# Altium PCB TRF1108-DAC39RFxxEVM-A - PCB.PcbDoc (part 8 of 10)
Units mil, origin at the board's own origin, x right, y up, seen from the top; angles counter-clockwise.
Board outline 4951.22 x 2726.56 mil, 16 copper layers (Top Layer, L2 GND1, L3 PWR1, L4 GND2, L5 PWR2, L6 GND3, L7 Ctrl Signal 1, L8 GND4, L9 GND5, L10 Ctrl Signal 2, L11 GND6, L12 PWR3, L13 GND7, L14 PWR4, L15 GND8, Bottom Layer), stack 80.2 mil thick; 705 components, 433 nets, 3633 pads, 1678 vias.
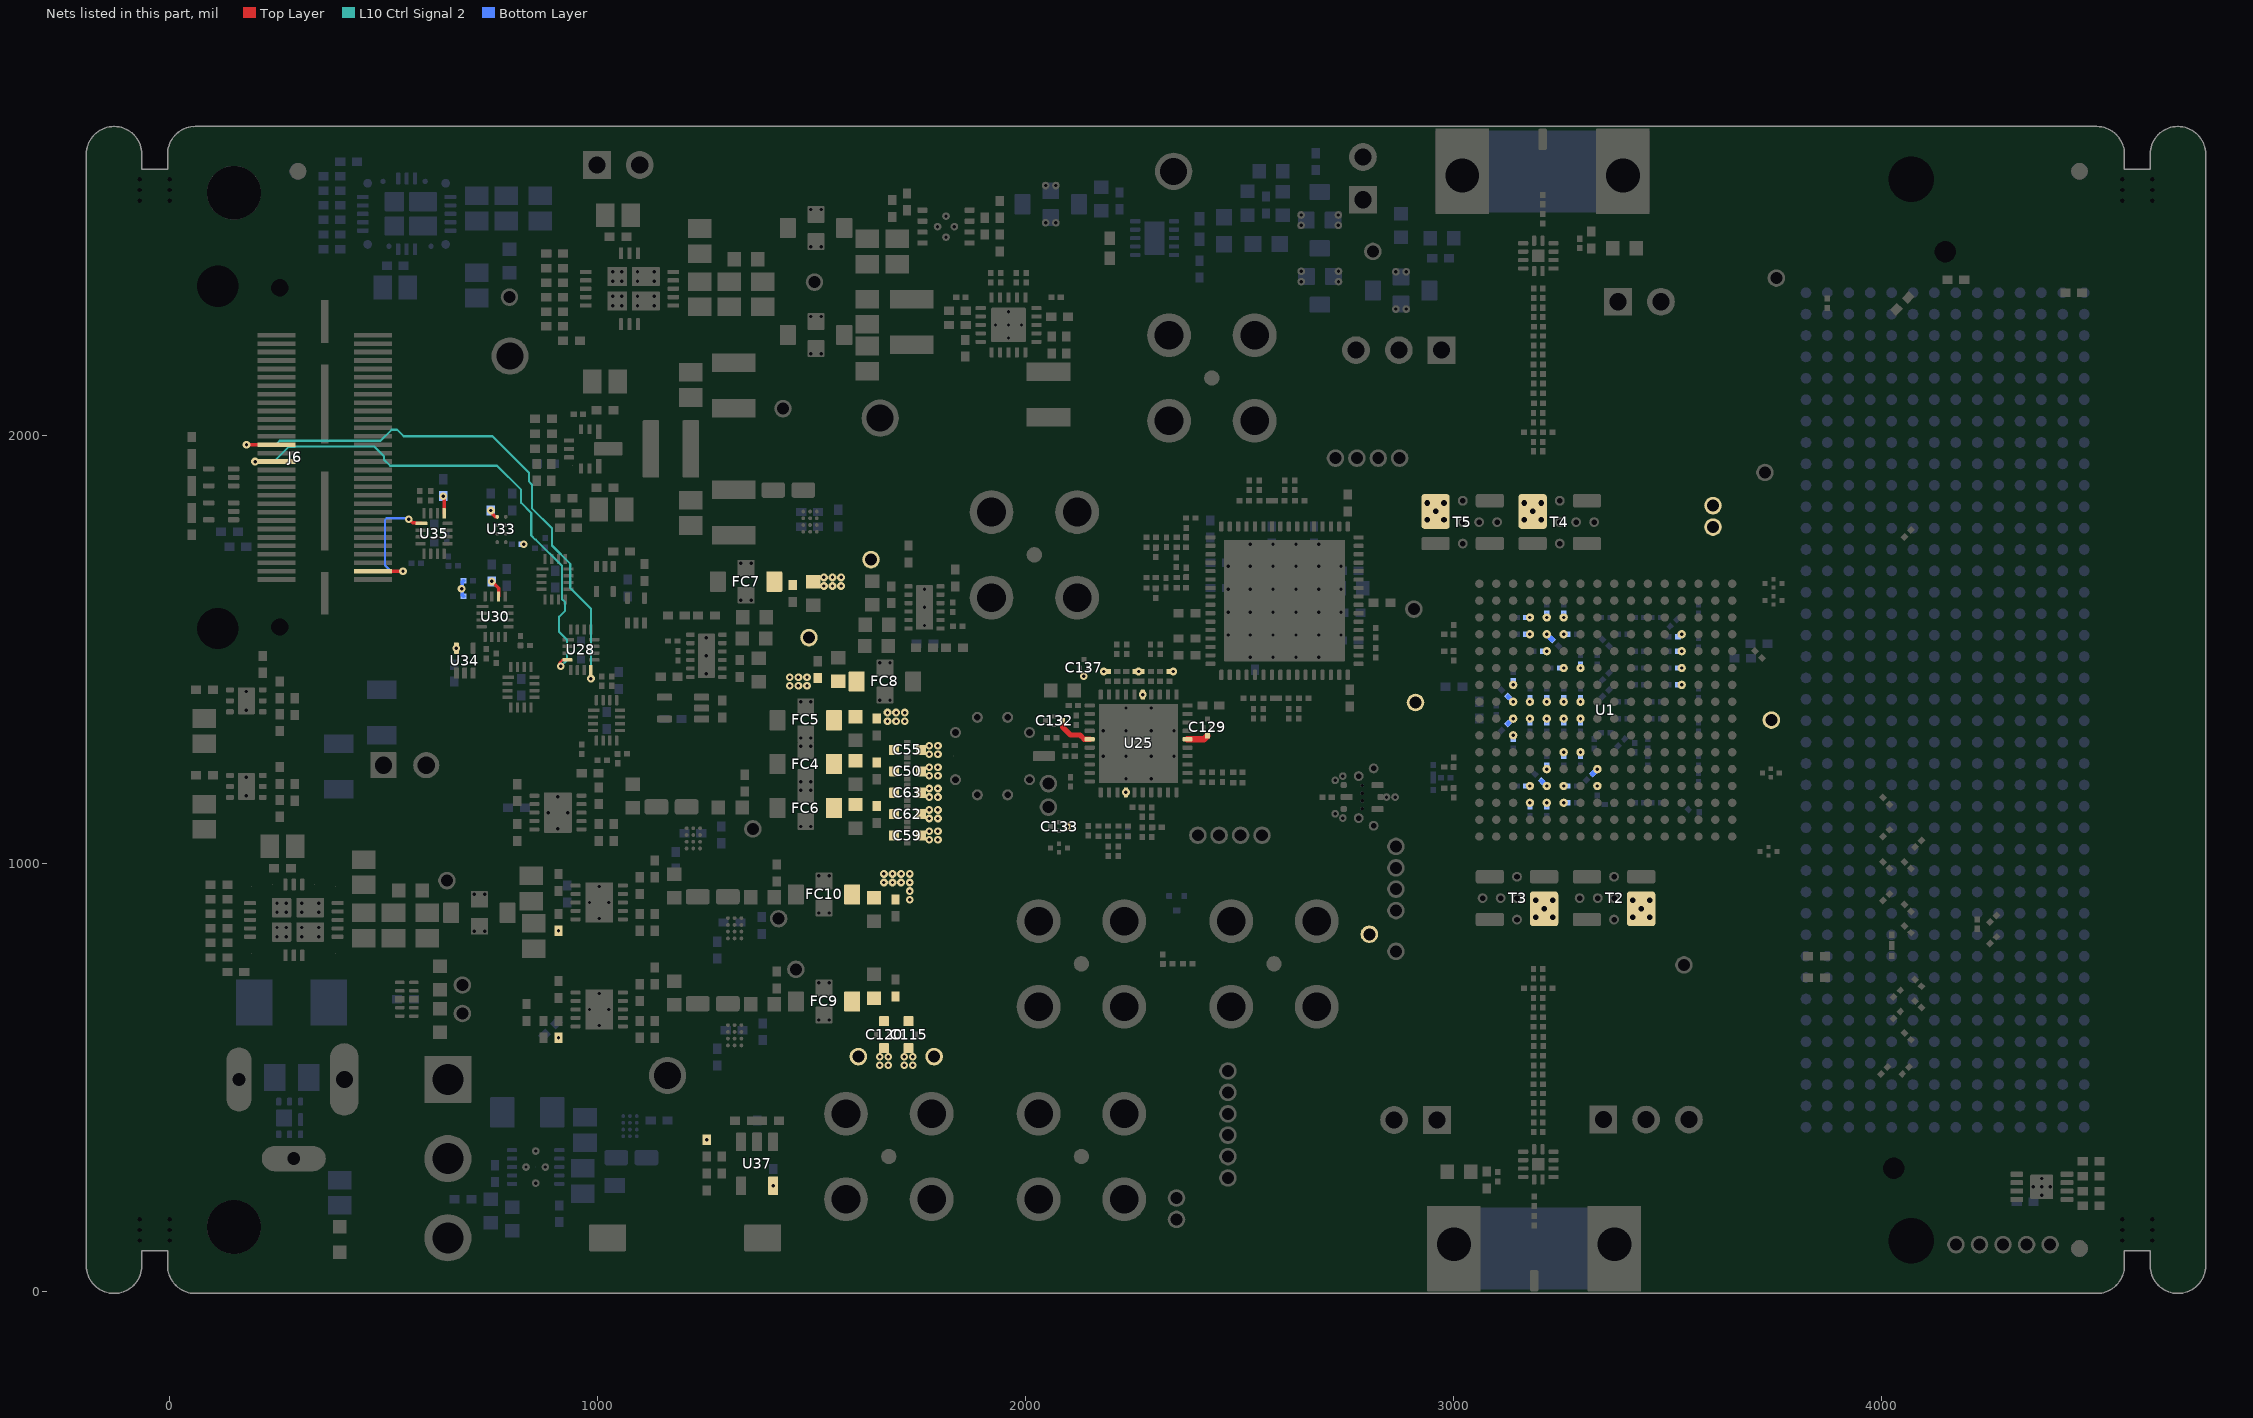
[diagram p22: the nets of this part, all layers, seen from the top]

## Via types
v1: diameter 18, hole 8, Top Layer to Bottom Layer, tented both sides, 1468 vias
v2: diameter 20, hole 10.01, Top Layer to Bottom Layer, 187 vias
v3: diameter 19.68, hole 7.87, Top Layer to Bottom Layer, tented both sides, 16 vias
v4: diameter 19.68, hole 7.87, Top Layer to Bottom Layer, 6 vias
v5: diameter 18/18/18/18/18/18/18/18/18/18/18/18/18/18/18/18 (per signal layer), hole 8, Top Layer to Bottom Layer, tented both sides, 1 vias

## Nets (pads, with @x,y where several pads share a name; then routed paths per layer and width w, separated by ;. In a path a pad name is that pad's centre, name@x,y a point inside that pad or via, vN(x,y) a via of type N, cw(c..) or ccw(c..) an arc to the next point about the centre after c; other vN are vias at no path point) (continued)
USB_LMX_SDI: J6.30 U28.4 | length 1237.6
  Top Layer w5: v1@908.95,1460.17 911.44,1462.66 911.44,1469.01 917.14,1474.72 928.49,1474.72 U28.4@928.95,1475.17
  Top Layer w8: v1(199.41,1938.46) J6.30@249.41,1938.46
  L10 Ctrl Signal 2 w5: v1(199.41,1938.46) 242.95,1938.46 276.83,1972.34 291.68,1972.34 292.99,1973.65 478.02,1973.65 500.29,1951.38 500.29,1943.48 514.96,1928.82 764.61,1928.82 821,1872.43 821,1841.97 844.64,1818.33 844.64,1765.74 854.14,1756.24 855.36,1756.24 916.5,1695.1 916.5,1617.2 923.82,1609.88 923.82,1590.13 909.92,1576.23 909.92,1540.33 928.37,1521.88 928.37,1474.59 v1(913.95,1460.17)
USB_LMX_SDO: J6.34 U28.8 | length 1347
  Top Layer w5: v1(984.07,1431.55) U28.8@984.07,1451.55
  Top Layer w8: v1(179.41,1977.83) J6.34@249.41,1977.83
  L10 Ctrl Signal 2 w5: v1(179.41,1977.83) 247.9,1977.83 257.09,1987.02 492.58,1987.02 518.58,2013.02 531.42,2013.02 546.92,1997.52 754.32,1997.52 839.04,1912.81 839.04,1892.18 846.09,1885.13 846.09,1829.61 893.07,1782.63 893.07,1742.32 935.95,1699.45 935.95,1643.29 984.07,1595.17 v1(984.07,1431.55)
USB_SCLK_DAC: J6.3 U35.1 | length 315.4
  Top Layer w8: J6.3@475,1682.56 v1(545,1682.56) ; v1(558.17,1804.05) 559.11,1804.05 567.86,1795.3 573.24,1795.3 574.5,1794.05 U35.1@588.17,1794.05
  Bottom Layer w5: v1(545,1682.56) 516.91,1682.56 502.72,1696.75 502.72,1801.7 507.18,1806.16 556.06,1806.16 v1(558.17,1804.05)
VCC01: C129.3 U25.16 | length 50.2
  Top Layer w15: U25.16@2377.76,1289.83 2416.39,1289.83 C129.3@2424.57,1298.02
VCC23: C132.3 U25.35 | length 90.3
  Top Layer w12: C132.3@2085.88,1333.18 2085.88,1318.12 2104.25,1299.75 2126.63,1299.75 2136.55,1289.83 U25.35@2149.41,1289.83
VCCCLKIN: C133.3 U25.4
  other v1: 2097.41,1085.82 2234.06,1165.82
VCCLOGIC: C137.3 R129.1 R130.1 R131.1 R132.1 U25.25 | length 35
  Top Layer w6: R130.1@2256.11,1448.17 v1(2263.59,1448.17) R131.1@2271.07,1448.17
  Top Layer w10: v1(2182.33,1448.17) R129.1@2192.33,1448.17 ; R132.1@2334.85,1448.17 v1(2344.85,1448.17)
  other v1: 2273.43,1394.17 2135.79,1437.02
VDDA: C50.1 C53.2 C54.2 C55.1 FC4.3
VDDA18A: C50.3 C248.2 C249.2 PP5.1 T2.3 T3.3 U1.G14 U1.H14 | length 25.5
  Bottom Layer w5: C248.2@3138.55,1290.07 v1(3138.55,1298.73)
  Bottom Layer w10: C249.2@3126.66,1326.21 v1(3138.55,1338.1)
  other v1: 1774.86,1204.73 1794.86,1204.73 1774.86,1224.73 1794.86,1224.73
VDDA18B: C55.3 C250.2 C251.2 PP6.1 T4.3 T5.3 U1.J14 U1.K14 | length 25.5
  Bottom Layer w5: v1(3138.55,1416.84) C251.2@3138.55,1425.5
  Bottom Layer w10: C250.2@3126.66,1389.36 v1(3138.55,1377.47)
  other v1: 1774.86,1254.73 1794.86,1254.73 1774.86,1274.73 1794.86,1274.73
VDDCLK10: C126.2 C127.2 C219.2 C220.2 C221.2 C222.2 C223.2 C224.2 FC10.3 U1.E12 U1.F11 U1.H11 U1.J11 U1.L11 U1.M12 | length 52
  Bottom Layer w5: C224.2@3208.62,1495.58 v1(3217.29,1495.58) ; v1(3217.29,1219.99) C219.2@3217.29,1228.65 ; C223.2@3248,1456.21 v1(3256.66,1456.21) ; C220.2@3256.66,1250.7 v1(3256.66,1259.36) ; C221.2@3256.66,1329.44 v1(3256.66,1338.1) ; v1(3256.66,1377.47) C222.2@3256.66,1386.13
  other v1: 1728.69,915.14 1728.69,935.14 1668.69,955.14 1688.69,955.14 1708.69,955.14 1728.69,955.14 1668.69,975.14 1688.69,975.14 1708.69,975.14 1728.69,975.14
VDDCLK18: C59.3 C225.2 C226.2 PP7.1 U1.H12 U1.H13 | length 17.3
  Bottom Layer w5: C226.2@3177.92,1329.44 v1(3177.92,1338.1) ; C225.2@3217.29,1329.44 v1(3217.29,1338.1)
  other v1: 1774.86,1054.73 1794.86,1054.73 1774.86,1074.73 1794.86,1074.73
VDDCSR: C59.1 C60.2 C61.2 C62.1 C63.1 FC6.3
VDDIO: C57.2 C58.2 C163.1 C166.1 C170.2 C172.2 C256.2 C257.2 FC5.3 R95.2 R104.2 R152.1 R153.1 R160.2 R170.2 U1.D9 U1.E9 U30.14 U33.A1 U34.5 U35.13 U37.5 | length 164.3
  Top Layer w8: v1(639.08,1857.84) 639.08,1855.13 641.32,1852.88 U35.13@641.32,1817.67 ; v1(750.54,1824.21) 750.54,1821.5 755,1817.05 755,1814.97 760.55,1809.41 U33.A1@765.34,1809.41 U33.A1@765.54,1809.21 ; v1(752.57,1658.54) 768.32,1642.79 U30.14@768.32,1623.54
  Bottom Layer w8: R153.1@686.9,1624.17 686.11,1624.17 683.81,1626.47 683.81,1636.9 681.9,1638.81 v1(681.9,1641.52) 681.9,1644.22 683.81,1646.14 683.81,1657.62 686.11,1659.91 R152.1@686.9,1659.91
  Bottom Layer w10: C257.2@3323.51,1208.1 v1(3335.4,1219.99)
  other v1: 1409.63,246.59 1254.63,354.1 908.37,592.32 908.37,842.32 3335.4,1180.62 1677.02,1332.09 1697.02,1332.09 1717.02,1332.09 1677.02,1352.09 1697.02,1352.09 1717.02,1352.09 669.58,1502.67 827.07,1745.36
VDDL: C115.1 C118.2 C119.2 C120.1 FC9.3
VDDLA: C115.3 C242.2 C243.2 PP14.1 U1.F10 U1.H10 | length 17.3
  Bottom Layer w5: C242.2@3296.03,1250.7 v1(3296.03,1259.36) ; C243.2@3296.03,1329.44 v1(3296.03,1338.1)
  other v1: 1716.05,528.18 1736.05,528.18 1716.05,548.18 1736.05,548.18
VDDLB: C120.3 C244.2 C245.2 PP15.1 U1.J10 U1.L10 | length 17.3
  Bottom Layer w5: v1(3296.03,1377.47) C244.2@3296.03,1386.13 ; v1(3296.03,1456.21) C245.2@3296.03,1464.87
  other v1: 1658.86,528.18 1678.86,528.18 1658.86,548.18 1678.86,548.18
VDDR: C63.3 C258.2 C259.2 C260.2 C261.2 PP9.1 U1.K4 U1.L4 U1.M4 U1.N4 | length 34.6
  Bottom Layer w5: C259.2@3523.59,1416.84 v1(3532.25,1416.84) ; C260.2@3523.59,1456.21 v1(3532.25,1456.21) ; C258.2@3523.59,1495.58 v1(3532.25,1495.58) ; C261.2@3523.59,1534.95 v1(3532.25,1534.95)
  other v1: 1774.86,1154.73 1794.86,1154.73 1774.86,1174.73 1794.86,1174.73
VDDSYS18: C62.3 C246.2 C247.2 PP8.1 U1.J12 U1.J13 | length 17.3
  Bottom Layer w5: v1(3177.92,1377.47) C247.2@3177.92,1386.13 ; v1(3217.29,1377.47) C246.2@3217.29,1386.13
  other v1: 1774.86,1104.73 1794.86,1104.73 1774.86,1124.73 1794.86,1124.73
VEExA: C101.2 C102.2 C236.1 C237.1 C238.1 C239.1 C240.1 C241.1 FC7.3 PP11.1 U1.C11 U1.C12 U1.C13 U1.D11 U1.D12 U1.D13 | length 60.1
  Bottom Layer w5: C238.1@3169.26,1180.62 v1(3177.92,1180.62) ; C236.1@3177.92,1132.59 v1(3177.92,1141.25) ; C239.1@3217.29,1132.59 v1(3217.29,1141.25) ; v1(3256.66,1141.25) C240.1@3265.32,1141.25 ; v1(3256.66,1180.62) C241.1@3265.32,1180.62
  Bottom Layer w10: C237.1@3205.4,1192.51 v1(3217.29,1180.62)
  other v1: 1528.48,1647.88 1548.48,1647.88 1568.48,1647.88 1528.48,1667.88 1548.48,1667.88 1568.48,1667.88
VEExB: C109.2 C110.2 C213.1 C214.1 C215.1 C216.1 C217.1 C218.1 FC8.3 PP12.1 U1.N11 U1.N12 U1.N13 U1.P11 U1.P12 U1.P13 | length 60.1
  Bottom Layer w5: C214.1@3169.26,1534.95 v1(3177.92,1534.95) ; C213.1@3169.26,1574.32 v1(3177.92,1574.32) ; v1(3217.29,1574.32) C218.1@3217.29,1582.98 ; v1(3256.66,1534.95) C216.1@3265.32,1534.95 ; v1(3256.66,1574.32) C217.1@3256.66,1582.98
  Bottom Layer w12: v1(3217.29,1534.95) C215.1@3229.18,1523.06
  other v1: 1448.87,1414.74 1468.87,1414.74 1488.87,1414.74 1448.87,1434.74 1468.87,1434.74 1488.87,1434.74
pads on no net: FID1.1 FID2.1 FID3.1 fid4.1 fid5.1 fid6.1 H3. H4. J1. J1.A2 J1.A3 J1.A6 J1.A7 J1.A10 J1.A11 J1.A14 J1.A15 J1.A18 J1.A19 J1.B1 J1.B4 J1.B5 J1.B8 J1.B9 J1.B12 J1.B13 J1.B16 J1.B17 J1.B40 J1.C6 J1.C7 J1.C10 J1.C11 J1.C14 J1.C15 J1.C16 J1.C18 J1.C19 J1.C22 J1.C23 J1.C39 J1.D8 J1.D9 J1.D11 J1.D12 J1.D14 J1.D15 J1.D16 J1.D17 J1.D18 J1.D20 J1.D21 J1.D23 J1.D24 J1.D29 J1.D33 J1.D34 J1.D36 J1.D38 J1.D40 J1.E2 J1.E3 J1.E6 J1.E7 J1.E9 J1.E10 J1.E12 J1.E13 J1.E15 J1.E16 J1.E17 J1.E18 J1.E19 J1.E21 J1.E22 J1.E24 J1.E25 J1.E27 J1.E28 J1.E30 J1.E31 J1.E33 J1.E34 J1.E36 J1.E37 J1.E39 J1.F4 J1.F5 J1.F7 J1.F8 J1.F10 J1.F11 J1.F13 J1.F14 J1.F15 J1.F16 J1.F17 J1.F18 J1.F19 J1.F20 J1.F22 J1.F23 J1.F25 J1.F26 J1.F28 J1.F29 J1.F31 J1.F32 J1.F34 J1.F35 J1.F37 J1.F38 J1.F40 J1.G2 J1.G3 J1.G15 J1.G16 J1.G17 J1.G18 J1.G19 J1.G21 J1.G22 J1.G24 J1.G25 J1.G39 J1.H1 J1.H4 J1.H5 J1.H7 J1.H8 J1.H10 J1.H11 J1.H13 J1.H14 J1.H15 J1.H16 J1.H17 J1.H19 J1.H20 J1.H22 J1.H23 J1.H40 J1.J2 J1.J3 J1.J4 J1.J5 J1.J6 J1.J7 J1.J9 J1.J10 J1.J12 J1.J13 J1.J15 J1.J16 J1.J17 J1.J18 J1.J19 J1.J21 J1.J22 J1.J24 J1.J25 J1.J27 J1.J28 J1.J30 J1.J31 J1.J33 J1.J34 J1.J36 J1.J37 J1.J39 J1.K1 J1.K2 J1.K3 J1.K4 J1.K5 J1.K7 J1.K8 J1.K10 J1.K11 J1.K12 J1.K13 J1.K14 J1.K15 J1.K16 J1.K17 J1.K19 J1.K20 J1.K22 J1.K23 J1.K25 J1.K26 J1.K28 J1.K29 J1.K31 J1.K32 J1.K34 J1.K35 J1.K37 J1.K38 J1.K40 J1.L3 J1.L4 J1.L5 J1.L7 J1.L8 J1.L9 J1.L10 J1.L12 J1.L13 J1.L15 J1.L16 J1.L17 J1.L19 J1.L20 J1.L21 J1.L24 J1.L25 J1.L28 J1.L29 J1.M2 J1.M3 J1.M4 J1.M5 J1.M6 J1.M7 J1.M10 J1.M11 J1.M12 J1.M14 J1.M15 J1.M17 J1.M18 J1.M19 J1.M20 J1.M22 J1.M23 J1.M26 J1.M27 J1.M30 J1.M31 J1.M34 J1.M35 J1.M38 J1.M39 J1.Y2 J1.Y3 J1.Y10 J1.Y11 J1.Y14 J1.Y15 J1.Y18 J1.Y19 J1.Y22 J1.Y23 J1.Y34 J1.Y35 J1.Y38 J1.Y39 J1.Z4 J1.Z5 J1.Z12 J1.Z13 J1.Z16 J1.Z17 J1.Z20 J1.Z21 J1.Z32 J1.Z33 J1.Z36 J1.Z37 J1.Z40 J2.3 J6.4@112.2,1548.31 J6.4@112.2,2348.31 J6.12 J6.15 J6.16 J6.17 J6.18 J6.21 J6.22 J6.23 J6.24 J6.39 J6.40 J6.41 J6.42 J6.45 J6.46 J6.47 J6.48 J6.51 J6.52 J6.53 J6.54 J6.55 J6.56 J6.57 J6.58 J6.59 J6.60 J6.MH1 J6.MH2 LBL1.0 Q1.0 SH-J13.0 SH-J14.0 SH-J17.0 SH-J18.0 T2.4 T3.4 T4.4 T5.4 U2.9 U3.A3 U3.B2 U3.C2 U4.7@179.22,1361.89 U4.7@179.22,1397.32 U5.3 U5.7@179.22,1161.89 U5.7@179.22,1197.32 U7.4 U10.A3 U10.B2 U10.C2 U11.4 U12.A3 U12.B2 U12.C2 U14.1 U14.2 U14.7 U14.8 U14.9 U14.13 U14.14 U14.15 U14.16 U14.22 U14.23 U14.29 U14.30 U14.31 U14.32 U14.40 U14.41 U14.43 U14.44 U14.46 U14.48 U14.49 U14.50 U14.51 U14.52 U14.59 U14.60 U14.61 U14.62 U14.63 U15.2 U15.11 U16.1 U17.2 U17.11 U18.A3 U18.B2 U18.C2 U20.A3 U20.B2 U20.C2 U25.18 U25.19 U25.21 U25.22 U25.29 U25.30 U27.3@537.69,682.32 U27.8@570.56,682.32 U30.4 U39.4 U40.11@2301.04,2439.12 U40.11@2301.04,2482.03

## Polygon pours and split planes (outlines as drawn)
VDDLB on L5 PWR2 "L5 PWR2-VDDLB" (solid, pour order 79): 467.47,0 4561.81,0 4561.81,2327.76 3284.03,2327.76 3284.03,1360 3845.9,1360 3845.9,415 1705.65,415 1705.65,577.74 467.47,577.74
GND on L5 PWR2 "L5_PWR2_GND_P111" (solid, remove dead copper, pour order 111): 3033.42,2342.8 3033.42,2132.24 3269.02,2132.24 3269.02,2342.8 4561.81,2342.8 4561.81,2716.54 0,2716.54 0,0 446,0 446,2342.8
5p5V_TRF_DCDC on L5 PWR2 "L5_PWR2_5P5V_TRF_DCDC_P110" (solid, remove dead copper, pour order 110): 3018.12,2631.37 3018.12,2132.24 309.41,2132.24 309.41,2631.37
VDDCLK10 on L5 PWR2 "L5 PWR2-VDDCLK10" (solid, pour order 44): 473.65,896.46 3268.98,896.46 3268.98,1232.32 3268.98,1484.8 3268.98,2105.59 473.65,2105.59
VDDLA on L5 PWR2 "L5_PWR2_VDDLA_P075" (solid, pour order 75): 1705.65,577.74 1705.65,415 3829.92,415 3829.92,1349.14 3284.03,1349.14 3284.03,879.93 467.47,879.93 467.47,577.74
5V_TRF on Bottom Layer "BOTTOM_LAYER_5V_TRF_P109" (solid, remove dead copper, pour order 109): 3074.22,287.69 3074.22,780.76 3006.28,848.7 2859.77,848.7 2779.37,768.3 2779.37,307.48 2832.11,254.74 3041.26,254.74
GND on Bottom Layer "BOTTOM_LAYER_GND_P116" (solid, remove dead copper, pour order 116): 0,0 4561.81,0 4561.81,2716.54 0,2716.54
NetC181_1 on Bottom Layer "BOTTOM_LAYER_NETC181_1_P115" (solid, remove dead copper, pour order 115): 2155.94,2539.89 2143.03,2552.8 2143.03,2563.51 2105.63,2563.51 2105.63,2502.91 2113.51,2495.02 2185.78,2495.02 2198.26,2482.55 2198.26,2447.97 2210.25,2435.98 2268,2435.98 2268,2504.92 2233.03,2539.89 2206.26,2539.89
3p3V_Utility on L12 PWR3 "L12 PWR3-3p3V_Utility" (solid, pour order 83): 1560.51,1731.83 1574.26,1745.58 1694.94,1745.58 1708.69,1731.83 1815.29,1731.83 1815.29,2716.54 0,2716.54 0,0 4561.81,0 4561.81,577.06 1886.85,577.06 1886.85,936.93 1481.35,936.93 1481.35,215 397.23,215 397.23,1932 1096.71,1932 1096.71,1166.89 1391.61,1166.89 1391.61,1731.83
3p3V_Utility on L12 PWR3 "L12_PWR3_3P3V_UTILITY_P052" (solid, remove dead copper, pour order 52): 2317.43,2403.47 2317.43,2323.86 2356.42,2284.87 2549.29,2284.87 2708.93,2125.23 2783.94,2125.23 2832.09,2173.39 2832.09,2270.26 2706.27,2396.08 2653.77,2448.59 2362.54,2448.59
GND on L12 PWR3 "L12_PWR3_GND_P117" (solid, pour order 117): 0,575.96 4561.81,575.96 4561.81,2716.54 0,2716.54
VEExA on L12 PWR3 "L12 PWR3-VEExA" (solid, pour order 85): 1391.91,1628.99 2872.03,1628.99 2872.03,1931.86 3822.81,1931.86 3822.81,1219.99 3138.55,1219.99 3138.55,952.06 4561.81,952.06 4561.81,2716.54 1820.34,2716.54 1820.34,1731.83 1391.91,1731.83
VDDA18A on L12 PWR3 "L12 PWR3-VDDA18A" (solid, pour order 89): 1886.85,921.63 1886.85,706.97 3501.53,706.97 3501.53,950 3139.12,950 3137.55,1219.99 3822.81,1219.99 3822.81,1352.31 3031.46,1352.31 3031.46,1235.13 1740.74,1235.13 1740.74,921.63
VDDA18B on L12 PWR3 "L12 PWR3-VDDA18B" (solid, pour order 104): 1740.74,1235.13 3031.46,1235.13 3031.46,1352.31 3822.81,1352.31 3822.81,1931.86 2872.03,1931.86 2872.03,1613.69 3335.4,1613.69 3335.4,1477.87 2898.82,1477.87 2898.82,1401.04 1740.74,1401.04
VDDIO on L12 PWR3 "L12 PWR3-VDDIO" (solid, pour order 72): 400,215 1481.35,215 1481.35,936.93 1740.62,936.93 1740.62,1368.99 1391.61,1368.99 1391.61,1166.89 1096.71,1166.89 1096.71,1932 400,1932
VEExB on L12 PWR3 "L12 PWR3-VEExB" (solid, pour order 106): 1391.61,1440.71 1391.61,1368.99 1740.62,1368.99 1740.62,1401.04 2898.82,1401.04 2898.82,1477.87 3335.4,1477.87 3335.4,1613.69 1391.61,1613.69 1391.61,1440.71
DVDD on L3 PWR1 "L3 PWR1-DVDD" (solid, pour order 112): 1430.65,0 4561.81,0 4561.81,2716.54 3020.83,2716.54 3020.83,865 2490.88,865 1886.85,865 1886.85,2146.75 1430.65,2146.75
2p5V_Clock on L3 PWR1 "L3 PWR1-2p5V_Clock" (solid, remove dead copper, pour order 95): 2143.25,1461.56 2177.71,1496.02 2366.79,1496.02 2368.74,1497.98 2368.74,2190 1180,2190 1180,1500 1040,1500 1040,1380 1430,1380 1430,1980 1886.85,1980 1886.85,865 2655.83,865 2655.83,1348.54 2631.73,1372.64 2379.28,1372.64 2355.18,1348.54 2163.81,1348.54 2108.42,1403.93 2108.42,1444.1 2125.89,1461.56
VCCLOGIC on L3 PWR1 "L3_PWR1_VCCLOGIC_P091" (solid, pour order 91): 2158.27,1451.93 2187.4,1481.06 2343.9,1481.06 2368.74,1456.21 2368.74,1389.75 2341.66,1362.67 2168.98,1362.67 2119.74,1412.18 2119.93,1447.44 2124.45,1451.93
5V_TRF on L3 PWR1 "L3_PWR1_5V_TRF_P030" (solid, remove dead copper, pour order 30): 2677.87,1263.46 2677.87,736.87 2761.36,653.37 3459.27,653.37 3516.92,711.02 3516.92,943.75 3296.03,1164.64 3296.03,1567.7 3415.6,1687.27 3488.2,1759.87 3488.2,2716.54 2707.65,2716.54 2707.65,2318.16 2885.35,2140.46 2885.35,1470.94
3p3V_Utility on L3 PWR1 "L3 PWR1-3p3V_Utility" (solid, pour order 108): 2368.74,2210 2368.74,2390.63 1784.99,2390.63 1784.99,2716.54 0,2716.54 0,0 1430.65,0 1430.65,2210
3p3V_Clock on L3 PWR1 "L3 PWR1-3p3V_Clock" (solid, pour order 107): 2368.74,1385.46 2639.08,1385.46 2662.28,1362.27 2751.61,1362.27 2864.85,1475.5 2864.85,2716.54 1800,2716.54 1800,2404.54 2390.31,2404.54
VCCCLKIN on L3 PWR1 "L3 PWR1-VCCCLKIN" (solid, pour order 77): 2067.41,1067.47 2102.9,1067.47 2120.05,1084.63 2120.05,1102.26 2144.43,1126.64 2280,1126.64 2280,1262.21 2067.41,1262.21
SYSREF_TERM on L3 PWR1 "L3_PWR1_SYSREF_TERM_P076" (solid, pour order 76): 2067.41,1054.73 2067.41,970.82 2280,970.82 2280,1111.35 2142.63,1111.35 2131.28,1100 2131.28,1075.34 2110.67,1054.73
12V_FMC on L14 PWR4 "L14_PWR4_12V_FMC_P016" (solid, pour order 16): 4561.81,0.73 4561.81,663.32 3675,663.32 1580,663.32 1580,200.63 455.8,200.63 455.8,0
12V on L14 PWR4 "L14_PWR4_12V_P017" (solid, pour order 17): 1580,658.66 1147.85,658.66 1147.85,2716.54 0,2716.54 0,0 455.8,0 455.8,200.63 1580,200.63
GND on L14 PWR4 "L14_PWR4_GND_P102" (solid, pour order 102): 4561.81,665 4561.81,2716.54 1155.97,2716.54 1155.97,665
VDDIO on L14 PWR4 "L14_PWR4_VDDIO_P078" (solid, pour order 78): 1521.69,1367.5 1521.69,739.03 3437.76,739.03 3437.76,1241.53 2840.8,1241.53 2840.8,943.46 1746.82,943.46 1746.82,1367.5
VDDR on L14 PWR4 "L14_PWR4_VDDR_P101" (solid, pour order 101): 1899.73,1142.11 1899.73,1546.64 3256.66,1546.64 3256.66,1365.43 3872.81,1365.43 3872.81,1900.62 1746.82,1900.62 1746.82,1142.11
VDDSYS18 on L14 PWR4 "L14_PWR4_VDDSYS18_P100" (solid, pour order 100): 3256.66,1350.14 3256.66,1546.64 1899.73,1546.64 1899.73,1142.11 1746.82,1142.11 1746.82,1085.38 2482.76,1085.38 2482.76,1350.14
VDDCLK18 on L14 PWR4 "L14_PWR4_VDDCLK18_P099" (solid, pour order 99): 3872.81,1241.53 2840.32,1241.53 2840.32,943.46 1746.82,943.46 1746.82,1085.38 2482.76,1085.38 2482.76,1350.14 3872.81,1350.14
3p8V_Clock_LDO on L14 PWR4 "L14_PWR4_3P8V_CLOCK_LDO_P000" (solid, pour order 0): 1310,1370 1310,2500 1667.12,2500 1667.12,1552.4 1490,1552.4 1490,1370
GND on L4 GND2 "L4_GND2_GND_P043" (solid, pour order 43): 0,0 4561.81,0 4561.81,2716.54 0,2716.54
GND on L7 Ctrl Signal 1 "L7_CTRL_SIGNAL_1_GND_P047" (solid, remove dead copper, pour order 47): 0,0 4561.81,0 4561.81,2716.54 0,2716.54
GND on L6 GND3 "L6_GND3_GND_P045" (solid, pour order 45): 0,0 4561.81,0 4561.81,2716.54 0,2716.54
GND on L8 GND4 "L8_GND4_GND_P048" (solid, pour order 48): 0,0 4561.81,0 4561.81,2716.54 0,2716.54
GND on L9 GND5 "L9_GND5_GND_P049" (solid, pour order 49): 0,0 4561.81,0 4561.81,2716.54 0,2716.54
GND on L10 Ctrl Signal 2 "L10_CTRL_SIGNAL_2_GND_P050" (solid, remove dead copper, pour order 50): 0,0 4561.81,0 4561.81,2716.54 0,2716.54
GND on L11 GND6 "L11_GND6_GND_P051" (solid, pour order 51): 0,0 4561.81,0 4561.81,2716.54 0,2716.54
GND on L13 GND7 "L13_GND7_GND_P053" (solid, pour order 53): 0,0 4561.81,0 4561.81,2716.54 0,2716.54
GND on L15 GND8 "L15_GND8_GND_P054" (solid, pour order 54): 0,0 4561.81,0 4561.81,2716.54 0,2716.54
no net on Top Solder "NONET_L-01_P-001" (solid): 3250.36,2456.67 3164.53,2456.67 3164.53,2721.55 3250.36,2721.55
no net on Top Solder "NONET_L-01_P-001" (solid): 3064.91,1870.62 3144.2,1949.92 3144.2,2380.86 3250.36,2380.86 3250.36,1950.04 3329.77,1870.63
no net on Top Solder "NONET_L-01_P-001" (solid): 3330.3,844.95 3251,765.65 3251,334.72 3144.85,334.72 3144.85,765.53 3065.43,844.95
no net on Top Solder "NONET_L-01_P-001" (solid): 3144.85,258.9 3230.68,258.9 3230.68,-5.01 3144.85,-5.01
2p3V_Analog_LDO on Top Layer "TOP_LAYER_2P3V_ANALOG_LDO_P114" (solid, remove dead copper, pour order 114): 863.65,1162.56 827.22,1162.56 821.71,1157.05 774.45,1157.05 751.86,1134.46 751.86,684.2 776.81,659.25 856.17,659.25 870.34,673.43 958.8,673.43 960.18,674.81 960.18,702.56 923.72,702.56 918.21,697.05 878.43,697.05 809.88,765.59 809.88,824.55 823.08,837.75 878.2,837.75 878.2,883.4 918.23,923.42 960.18,923.42 960.18,951.17 954.38,956.97 924.52,956.97 914.59,947.05 886.19,947.05 872.2,933.06 817.08,933.06 793.17,956.97 793.17,1114.73 811.87,1133.43 862.3,1133.43 863.65,1134.77
NetC117_2 on Top Layer "TOP_LAYER_NETC117_2_P121" (solid, remove dead copper, pour order 121): 1398.15,651.99 1480.94,651.99 1491.47,662.52 1491.47,763.7 1476.57,778.6 1450.38,778.6 1438.82,767.04 1438.82,726.72 1433.17,721.07 1398.5,721.07 1395,717.57 1395,655.14
GND on Top Layer "TOP_LAYER_GND_P122" (solid, remove dead copper, pour order 122): 0,0 4561.81,0 4561.81,2716.54 0,2716.54
GND on L2 GND1 "L2_GND1_GND_P120" (solid, pour order 120): 86.41,0 4561.81,0 4561.81,2716.54 0,2716.54 0,86.41 ccw(c86.41,86.41)

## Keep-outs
Top Layer:
  circle w0.1: c4461.81,100 r20
  circle w0.1: c4461.81,2616.54 r20
  circle w0.1: c300,2616.53 r20
Bottom Layer:
  circle w0.1: c4461.81,2616.54 r20
  circle w0.1: c299.41,2616.46 r20
  circle w0.1: c4461.81,100 r20
Keep-Out Layer:
  text ".Layer_Name" at 680.5,-1357.4 h60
